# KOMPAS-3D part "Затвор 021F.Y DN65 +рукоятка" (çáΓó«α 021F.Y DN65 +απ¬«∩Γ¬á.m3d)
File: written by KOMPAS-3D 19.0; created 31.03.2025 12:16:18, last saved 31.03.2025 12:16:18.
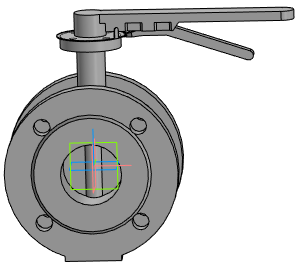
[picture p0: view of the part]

Document properties: Автор: Евгений; Полное имя файла: Затвор 021F.Y DN65 +рукоятка.a3d

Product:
- Part/product: Затвор 021F.Y DN65 +рукоятка
    Масса: 10.9856

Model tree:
1. Операция без истории:1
